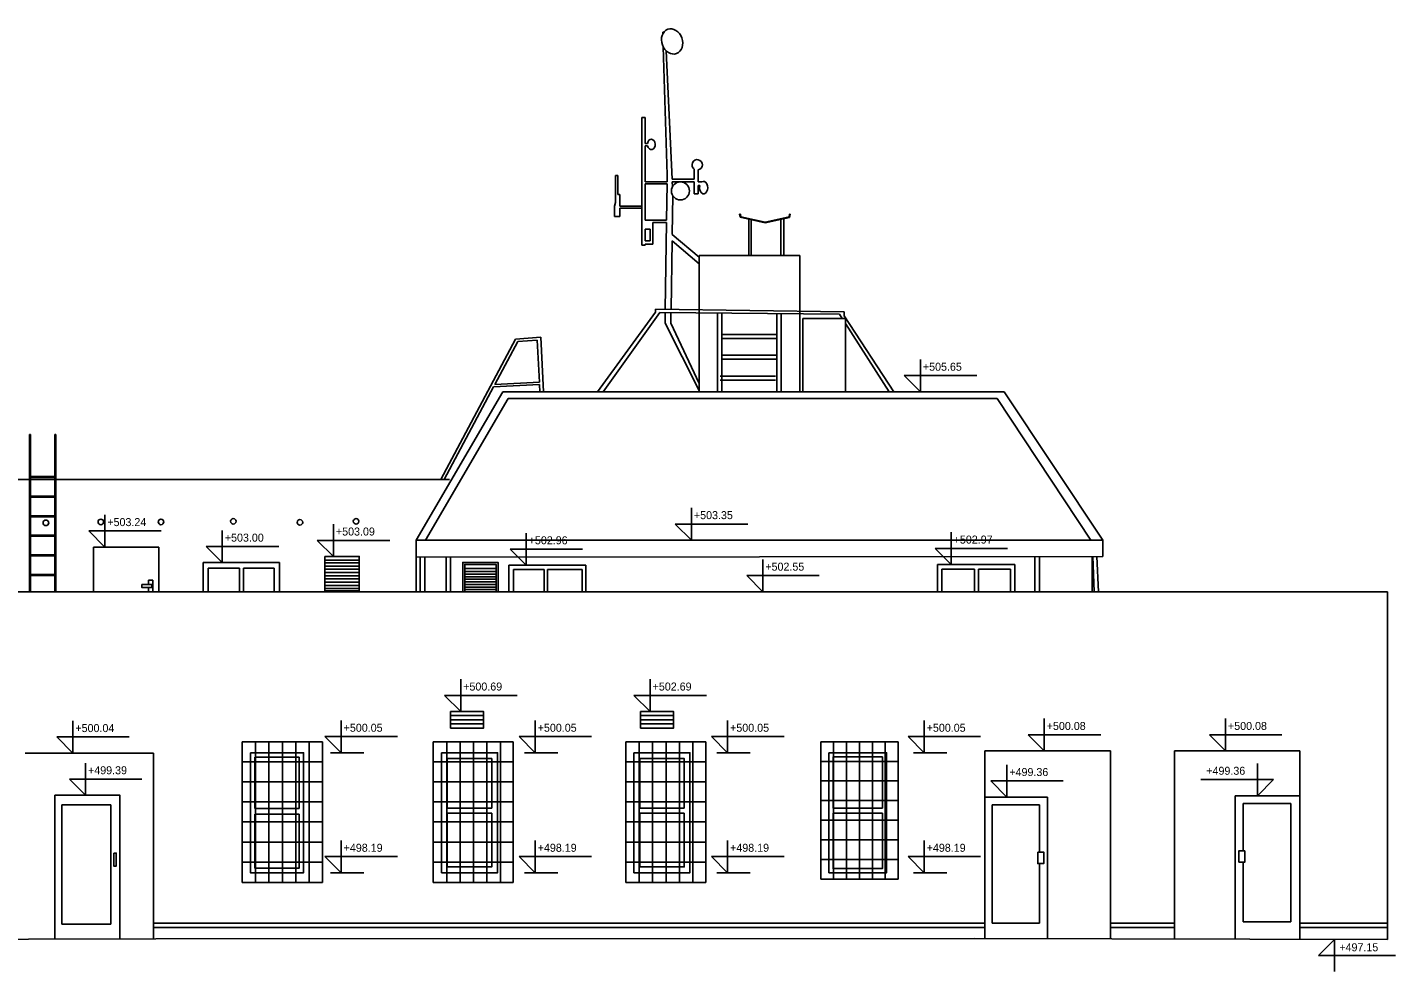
# Model space of a CAD drawing. Extents: x 224 to 311.2, y 493.1 to 511.4.
# Drawn here: x 290.02 to 311.23, y 496.65 to 511.3 of the extents above; entities that cross this region are included whole.
import ezdxf

# ---------------------------------------------------------------- set-up
doc = ezdxf.new("R2010")
doc.units = 0
for name, color, linetype in [('antena', 7, 'Continuous'), ('dvere', 7, 'Continuous'), ('mriz', 7, 'Continuous'), ('okap', 7, 'Continuous'), ('okna', 7, 'Continuous'), ('strecha_sikma', 7, 'Continuous'), ('teren', 7, 'Continuous'), ('vyustky_vzduchotechniky', 7, 'Continuous'), ('zakl_tenka', 7, 'Continuous'), ('zebrik', 7, 'Continuous'), ('znaceni', 7, 'Continuous')]:
    doc.layers.add(name, color=color, linetype=linetype)

msp = doc.modelspace()

# ---------------------------------------------------------------- linework, layer by layer
at = {"layer": 'antena'}
for p, q in [((299.871, 511.222), (299.887, 511.222)), ((299.872, 511.198), (299.871, 511.222)), ((299.939, 509.008), (299.878, 510.995)), ((299.924, 510.933), (300.015, 508.944)), ((299.547, 509.897), (299.547, 507.917)), ((299.547, 509.897), (299.597, 509.897)), ((299.597, 509.897), (299.597, 509.497)), ((299.597, 509.497), (299.634, 509.497)), ((299.597, 509.457), (299.636, 509.457)), ((299.597, 509.457), (299.597, 508.899)), ((299.138, 508.999), (299.138, 508.579)), ((299.172, 508.999), (299.138, 508.999)), ((299.172, 508.704), (299.172, 508.999)), ((299.938, 508.899), (299.939, 509.008)), ((300.358, 509.1), (300.358, 508.944)), ((300.418, 509.087), (300.418, 508.899)), ((299.597, 508.899), (299.938, 508.899)), ((299.597, 508.868), (299.938, 508.868)), ((299.597, 508.868), (299.597, 508.308)), ((299.93, 508.308), (299.938, 508.868)), ((300.015, 508.944), (300.358, 508.944)), ((300.017, 508.899), (300.358, 508.899)), ((300.017, 508.899), (300.021, 508.828)), ((300.358, 508.899), (300.358, 508.716)), ((300.478, 508.899), (300.418, 508.899)), ((300.445, 508.842), (300.418, 508.842)), ((300.418, 508.842), (300.418, 508.716)), ((299.138, 508.579), (299.123, 508.524)), ((299.203, 508.704), (299.172, 508.704)), ((299.203, 508.524), (299.203, 508.704)), ((300.024, 508.689), (300.015, 508.085)), ((300.358, 508.716), (300.418, 508.716)), ((299.123, 508.524), (299.123, 508.364)), ((299.123, 508.364), (299.203, 508.364)), ((299.547, 508.524), (299.203, 508.524)), ((299.547, 508.493), (299.203, 508.493)), ((299.203, 508.364), (299.203, 508.493)), ((299.93, 508.308), (299.597, 508.308)), ((299.597, 508.168), (299.677, 508.168)), ((299.597, 508.168), (299.597, 507.988)), ((299.677, 508.168), (299.677, 507.988)), ((299.718, 508.273), (299.929, 508.273)), ((299.718, 508.273), (299.718, 507.933)), ((299.91, 506.923), (299.929, 508.273)), ((299.677, 507.988), (299.597, 507.988)), ((300.014, 507.986), (299.999, 506.922)), ((300.014, 507.986), (300.437, 507.63)), ((300.015, 508.085), (300.437, 507.731)), ((299.547, 507.917), (299.597, 507.917)), ((299.718, 507.933), (299.597, 507.933)), ((299.597, 507.933), (299.597, 507.917)), ((299.907, 506.709), (299.909, 506.872)), ((299.907, 506.709), (300.437, 505.668)), ((299.998, 506.871), (299.996, 506.709)), ((300.437, 505.772), (299.996, 506.709))]:
    msp.add_line(p, q, dxfattribs=at)
msp.add_circle((300.144, 508.761), 0.14, dxfattribs=at)
msp.add_arc((300.404, 509.166), 0.08, 280.3791, 235.261, dxfattribs=at)
msp.add_ellipse((300.016, 511.078), major_axis=(-0.068, 0.188), ratio=0.8, dxfattribs=at)
for centre, major_axis, ratio, start_param, end_param in [((299.693, 509.482), (0, 0.08), 0.75, 1.88862, 7.665365), ((300.504, 508.812), (0, 0.096), 0.653945, 1.246279, 6.710051)]:
    msp.add_ellipse(centre, major_axis=major_axis, ratio=ratio, start_param=start_param, end_param=end_param, dxfattribs=at)
at = {"layer": 'dvere'}
for p, q in [((290.557, 499.241), (291.314, 499.241)), ((290.557, 499.241), (290.557, 497.391)), ((291.314, 499.241), (291.314, 497.391)), ((290.557, 497.391), (291.314, 497.391))]:
    msp.add_line(p, q, dxfattribs=at)
msp.add_lwpolyline([(291.362, 498.493), (291.4, 498.493), (291.4, 498.29), (291.362, 498.29)], close=True, dxfattribs=at)
at = {"layer": 'mriz'}
for p, q in [((293.353, 500.219), (294.597, 500.219)), ((293.353, 500.219), (293.353, 498.039)), ((293.56, 500.219), (293.56, 498.039)), ((293.767, 500.219), (293.767, 498.039)), ((293.974, 500.219), (293.974, 498.039)), ((294.181, 500.219), (294.181, 498.039)), ((294.388, 500.219), (294.388, 498.039)), ((294.597, 500.219), (294.597, 498.039)), ((296.314, 500.219), (297.554, 500.219)), ((296.314, 500.219), (296.314, 498.039)), ((296.522, 500.219), (296.522, 498.039)), ((296.73, 500.219), (296.73, 498.039)), ((296.938, 500.219), (296.938, 498.039)), ((297.146, 500.219), (297.146, 498.039)), ((297.354, 500.219), (297.354, 498.039)), ((297.554, 500.219), (297.554, 498.039)), ((299.297, 500.219), (300.537, 500.219)), ((299.297, 500.219), (299.297, 498.039)), ((299.505, 500.219), (299.505, 498.039)), ((299.713, 500.219), (299.713, 498.039)), ((299.921, 500.219), (299.921, 498.039)), ((300.129, 500.219), (300.129, 498.039)), ((300.337, 500.219), (300.337, 498.039)), ((300.537, 500.219), (300.537, 498.039)), ((302.319, 500.219), (303.519, 500.219)), ((302.319, 500.219), (302.319, 498.089)), ((302.519, 500.219), (302.519, 498.089)), ((302.719, 500.219), (302.719, 498.089)), ((302.919, 500.219), (302.919, 498.089)), ((303.119, 500.219), (303.119, 498.089)), ((303.319, 500.219), (303.319, 498.089)), ((303.519, 500.219), (303.519, 498.089)), ((293.353, 499.908), (294.597, 499.908)), ((296.314, 499.908), (297.554, 499.908)), ((299.297, 499.908), (300.537, 499.908)), ((302.319, 499.915), (303.519, 499.915)), ((293.353, 499.597), (294.597, 499.597)), ((296.314, 499.597), (297.554, 499.597)), ((299.297, 499.597), (300.537, 499.597)), ((302.319, 499.611), (303.519, 499.611)), ((293.353, 499.286), (294.597, 499.286)), ((296.314, 499.286), (297.554, 499.286)), ((299.297, 499.286), (300.537, 499.286)), ((302.319, 499.307), (303.519, 499.307)), ((293.353, 498.975), (294.597, 498.975)), ((296.314, 498.975), (297.554, 498.975)), ((299.297, 498.975), (300.537, 498.975)), ((302.319, 499.003), (303.519, 499.003)), ((293.353, 498.664), (294.597, 498.664)), ((296.314, 498.664), (297.554, 498.664)), ((299.297, 498.664), (300.537, 498.664)), ((302.319, 498.699), (303.519, 498.699)), ((302.319, 498.395), (303.519, 498.395)), ((293.353, 498.353), (294.597, 498.353)), ((296.314, 498.353), (297.554, 498.353)), ((299.297, 498.353), (300.537, 498.353)), ((293.353, 498.039), (294.597, 498.039)), ((296.314, 498.039), (297.554, 498.039)), ((299.297, 498.039), (300.537, 498.039)), ((302.319, 498.089), (303.519, 498.089))]:
    msp.add_line(p, q, dxfattribs=at)
at = {"layer": 'okap'}
for p, q in [((296.048, 503.345), (296.048, 503.081)), ((306.689, 503.345), (306.689, 503.091)), ((306.689, 503.091), (296.048, 503.081)), ((296.048, 503.081), (296.048, 502.546)), ((296.112, 503.081), (296.112, 502.546)), ((296.512, 503.082), (296.512, 502.546)), ((296.578, 503.082), (296.578, 502.546)), ((305.638, 503.09), (305.638, 502.546)), ((305.712, 503.09), (305.712, 502.546)), ((306.534, 503.091), (306.557, 502.546)), ((306.601, 503.091), (306.625, 502.546))]:
    msp.add_line(p, q, dxfattribs=at)
at = {"layer": 'okna'}
for p, q in [((292.824, 502.912), (292.824, 502.546)), ((292.824, 502.912), (293.308, 502.912)), ((293.308, 502.912), (293.308, 502.546)), ((293.372, 502.912), (293.372, 502.546)), ((293.372, 502.912), (293.849, 502.912)), ((293.849, 502.912), (293.849, 502.546)), ((297.558, 502.889), (298.033, 502.889)), ((297.558, 502.889), (297.558, 502.546)), ((298.033, 502.889), (298.033, 502.546)), ((298.086, 502.889), (298.086, 502.546)), ((298.086, 502.889), (298.621, 502.889)), ((298.621, 502.889), (298.621, 502.546)), ((304.196, 502.897), (304.196, 502.546)), ((304.196, 502.897), (304.7, 502.897)), ((304.7, 502.897), (304.7, 502.546)), ((304.764, 502.897), (304.764, 502.546)), ((304.764, 502.897), (305.26, 502.897)), ((305.26, 502.897), (305.26, 502.546)), ((309.603, 499.26), (308.869, 499.26)), ((308.869, 499.26), (308.869, 498.529)), ((309.603, 499.26), (309.603, 497.426)), ((293.55, 499.183), (294.233, 499.183)), ((293.55, 499.097), (294.233, 499.097)), ((296.531, 499.191), (297.221, 499.191)), ((296.531, 499.111), (297.221, 499.111)), ((299.513, 499.191), (300.203, 499.191)), ((299.513, 499.111), (300.203, 499.111)), ((302.511, 499.191), (303.275, 499.191)), ((302.511, 499.111), (303.275, 499.111)), ((304.975, 499.239), (305.709, 499.239)), ((304.975, 499.239), (304.975, 497.405)), ((305.709, 499.239), (305.709, 498.508)), ((305.709, 498.331), (305.709, 497.405)), ((308.869, 498.352), (308.869, 497.426)), ((304.975, 497.405), (305.709, 497.405)), ((309.603, 497.426), (308.869, 497.426))]:
    msp.add_line(p, q, dxfattribs=at)
for points in [[(293.55, 499.183), (293.55, 499.979), (294.233, 499.979), (294.233, 499.183)], [(296.531, 499.191), (296.531, 499.959), (297.221, 499.959), (297.221, 499.191)], [(299.513, 499.191), (299.513, 499.959), (300.203, 499.959), (300.203, 499.191)], [(302.511, 499.191), (302.511, 499.984), (303.275, 499.984), (303.275, 499.191)], [(294.233, 499.097), (294.233, 498.257), (293.55, 498.257), (293.55, 499.097)], [(297.221, 499.111), (297.221, 498.277), (296.531, 498.277), (296.531, 499.111)], [(300.203, 499.111), (300.203, 498.277), (299.513, 498.277), (299.513, 499.111)], [(303.275, 499.111), (303.275, 498.252), (302.511, 498.252), (302.511, 499.111)]]:
    msp.add_lwpolyline(points, dxfattribs=at)
for points in [[(305.684, 498.508), (305.777, 498.508), (305.777, 498.331), (305.684, 498.331)], [(308.894, 498.529), (308.801, 498.529), (308.801, 498.352), (308.894, 498.352)]]:
    msp.add_lwpolyline(points, close=True, dxfattribs=at)
at = {"layer": 'strecha_sikma'}
for p, q in [((297.391, 505.647), (296.048, 503.345)), ((297.391, 505.647), (305.163, 505.647)), ((305.163, 505.647), (306.689, 503.345)), ((297.475, 505.54), (296.194, 503.345)), ((297.475, 505.54), (305.054, 505.54)), ((305.054, 505.54), (306.508, 503.345)), ((296.048, 503.345), (306.689, 503.345))]:
    msp.add_line(p, q, dxfattribs=at)
at = {"layer": 'teren'}
msp.add_line((304.698, 497.168), (311.105, 497.152), dxfattribs=at)
msp.add_lwpolyline([(260.099, 497.175), (263.904, 497.145), (275.27, 497.123), (276.223, 497.121), (292.012, 497.161), (304.698, 497.168)], dxfattribs=at)
at = {"layer": 'vyustky_vzduchotechniky'}
for p, q in [((294.63, 503.033), (295.166, 503.033)), ((294.63, 502.993), (295.166, 502.993)), ((294.63, 502.943), (295.166, 502.943)), ((294.63, 502.893), (295.166, 502.893)), ((296.8, 502.908), (297.286, 502.908)), ((296.8, 502.858), (297.286, 502.858)), ((294.63, 502.843), (295.166, 502.843)), ((294.63, 502.793), (295.166, 502.793)), ((294.63, 502.743), (295.166, 502.743)), ((294.63, 502.693), (295.166, 502.693)), ((294.63, 502.643), (295.166, 502.643)), ((296.8, 502.818), (297.286, 502.818)), ((296.8, 502.778), (297.286, 502.778)), ((296.8, 502.738), (297.286, 502.738)), ((296.8, 502.698), (297.286, 502.698)), ((296.8, 502.658), (297.286, 502.658)), ((294.63, 502.593), (295.166, 502.593)), ((296.8, 502.618), (297.286, 502.618)), ((296.8, 502.578), (297.286, 502.578)), ((296.581, 500.624), (297.092, 500.624)), ((296.581, 500.56), (297.092, 500.56)), ((299.526, 500.624), (300.037, 500.624)), ((299.526, 500.56), (300.037, 500.56)), ((296.581, 500.496), (297.092, 500.496)), ((299.526, 500.496), (300.037, 500.496))]:
    msp.add_line(p, q, dxfattribs=at)
for points in [[(294.63, 503.092), (295.166, 503.092), (295.166, 502.557), (294.63, 502.557)], [(296.581, 500.688), (297.092, 500.688), (297.092, 500.431), (296.581, 500.431)], [(299.526, 500.688), (300.037, 500.688), (300.037, 500.431), (299.526, 500.431)]]:
    msp.add_lwpolyline(points, close=True, dxfattribs=at)
for points in [[(296.769, 502.546), (296.769, 503), (297.317, 503), (297.317, 502.546)], [(296.8, 502.546), (296.8, 502.969), (297.286, 502.969), (297.286, 502.546)]]:
    msp.add_lwpolyline(points, dxfattribs=at)
at = {"layer": 'zakl_tenka'}
for p, q in [((300.437, 507.76), (300.437, 505.647)), ((301.994, 507.76), (301.994, 505.647)), ((302.043, 506.782), (302.043, 505.647)), ((302.704, 506.782), (302.043, 506.782)), ((302.704, 506.782), (302.704, 505.647)), ((281.454, 504.283), (296.565, 504.283)), ((291.046, 503.237), (291.046, 502.546)), ((291.046, 503.237), (292.057, 503.237)), ((292.057, 503.237), (292.057, 502.546)), ((296.184, 503.081), (296.184, 502.546)), ((306.524, 503.091), (306.524, 502.546)), ((292.745, 502.996), (293.931, 502.996)), ((292.745, 502.996), (292.745, 502.546)), ((293.931, 502.996), (293.931, 502.546)), ((297.483, 502.955), (297.483, 502.546)), ((297.483, 502.955), (298.679, 502.955)), ((298.679, 502.955), (298.679, 502.546)), ((304.131, 502.967), (304.131, 502.546)), ((304.131, 502.967), (305.33, 502.967)), ((305.33, 502.967), (305.33, 502.546)), ((279.583, 502.546), (311.105, 502.546)), ((311.105, 502.546), (311.105, 497.152)), ((289.987, 500.043), (291.975, 500.043)), ((291.975, 500.043), (291.975, 497.161)), ((304.864, 500.077), (306.81, 500.077)), ((304.864, 500.077), (304.864, 497.167)), ((306.81, 500.077), (306.81, 497.163)), ((307.8, 500.077), (309.746, 500.077)), ((307.8, 500.077), (307.8, 497.16)), ((309.746, 500.077), (309.746, 497.155)), ((304.864, 499.361), (305.833, 499.361)), ((305.833, 499.361), (305.833, 497.165)), ((309.746, 499.382), (308.745, 499.382)), ((308.745, 499.382), (308.745, 497.158)), ((291.975, 497.405), (304.864, 497.405)), ((291.975, 497.339), (304.864, 497.339)), ((306.81, 497.405), (307.8, 497.405)), ((306.81, 497.339), (307.8, 497.339)), ((309.746, 497.405), (311.105, 497.405)), ((309.746, 497.339), (311.105, 497.339))]:
    msp.add_line(p, q, dxfattribs=at)
for points in [[(301.994, 507.76), (300.437, 507.76)], [(291.9, 502.659), (291.9, 502.722), (291.964, 502.722), (291.964, 502.546)], [(291.9, 502.546), (291.9, 502.612)], [(290.449, 497.157), (290.449, 499.389), (291.456, 499.389), (291.456, 497.16)]]:
    msp.add_lwpolyline(points, dxfattribs=at)
for points in [[(291.796, 502.659), (291.951, 502.659), (291.951, 502.612), (291.796, 502.612)], [(293.48, 500.048), (294.302, 500.048), (294.302, 498.188), (293.48, 498.188)], [(296.442, 500.048), (297.31, 500.048), (297.31, 498.188), (296.442, 498.188)], [(299.424, 500.048), (300.292, 500.048), (300.292, 498.188), (299.424, 498.188)], [(302.447, 500.048), (303.339, 500.048), (303.339, 498.188), (302.447, 498.188)]]:
    msp.add_lwpolyline(points, close=True, dxfattribs=at)
for centre in [(290.309, 503.613), (291.161, 503.628), (292.093, 503.628), (293.214, 503.637), (294.247, 503.621), (295.117, 503.637)]:
    msp.add_circle(centre, 0.0431, dxfattribs=at)
at = {"layer": 'zebrik'}
for p, q in [((301.059, 508.399), (301.068, 508.351)), ((301.059, 508.399), (301.074, 508.399)), ((301.074, 508.4), (301.081, 508.358)), ((301.828, 508.356), (301.836, 508.398)), ((301.836, 508.348), (301.847, 508.398)), ((301.847, 508.398), (301.836, 508.398)), ((301.068, 508.351), (301.459, 508.268)), ((301.081, 508.358), (301.46, 508.278)), ((301.202, 508.322), (301.202, 507.76)), ((301.242, 508.314), (301.242, 507.76)), ((301.459, 508.268), (301.836, 508.348)), ((301.46, 508.278), (301.828, 508.356)), ((301.702, 508.32), (301.702, 507.76)), ((301.747, 508.329), (301.747, 507.76)), ((299.756, 506.881), (298.86, 505.647)), ((299.756, 506.926), (302.683, 506.883)), ((299.756, 506.926), (299.756, 506.881)), ((302.683, 506.883), (302.683, 506.824)), ((299.823, 506.873), (298.945, 505.647)), ((299.823, 506.873), (302.609, 506.85)), ((300.721, 506.865), (300.721, 505.647)), ((300.786, 506.865), (300.786, 505.647)), ((301.641, 506.858), (301.641, 505.647)), ((301.706, 506.857), (301.706, 505.647)), ((302.609, 506.85), (302.653, 506.782)), ((302.683, 506.824), (303.452, 505.647)), ((302.704, 506.702), (303.381, 505.647)), ((297.588, 506.463), (296.428, 504.283)), ((297.588, 506.463), (297.978, 506.491)), ((297.978, 506.491), (298.022, 505.647)), ((300.786, 506.534), (301.641, 506.534)), ((300.786, 506.474), (301.641, 506.474)), ((297.623, 506.427), (297.268, 505.759)), ((297.623, 506.427), (297.925, 506.448)), ((297.925, 506.448), (297.959, 505.795)), ((300.783, 506.214), (301.638, 506.214)), ((300.783, 506.154), (301.638, 506.154)), ((300.761, 505.888), (301.616, 505.888)), ((300.761, 505.828), (301.616, 505.828)), ((297.247, 505.72), (296.483, 504.283)), ((297.247, 505.72), (297.961, 505.757)), ((297.268, 505.759), (297.959, 505.795)), ((297.961, 505.757), (297.967, 505.647)), ((290.056, 504.984), (290.056, 502.546)), ((290.056, 504.984), (290.071, 504.984)), ((290.071, 504.984), (290.071, 504.334)), ((290.446, 504.984), (290.461, 504.984)), ((290.446, 504.984), (290.446, 504.334)), ((290.461, 504.984), (290.461, 502.546)), ((290.071, 504.334), (290.446, 504.334)), ((290.071, 504.319), (290.446, 504.319)), ((290.071, 504.319), (290.071, 504.029)), ((290.446, 504.319), (290.446, 504.029)), ((290.071, 504.029), (290.446, 504.029)), ((290.071, 504.014), (290.446, 504.014)), ((290.071, 504.014), (290.071, 503.724)), ((290.446, 504.014), (290.446, 503.724)), ((290.071, 503.724), (290.446, 503.724)), ((290.071, 503.709), (290.446, 503.709)), ((290.071, 503.709), (290.071, 503.42)), ((290.446, 503.709), (290.446, 503.42)), ((290.071, 503.42), (290.446, 503.42)), ((290.071, 503.405), (290.446, 503.405)), ((290.071, 503.405), (290.071, 503.115)), ((290.446, 503.405), (290.446, 503.115)), ((290.071, 503.115), (290.446, 503.115)), ((290.071, 503.1), (290.446, 503.1)), ((290.071, 503.1), (290.071, 502.81)), ((290.446, 503.1), (290.446, 502.81)), ((290.071, 502.81), (290.446, 502.81)), ((290.071, 502.795), (290.446, 502.795)), ((290.071, 502.795), (290.071, 502.546)), ((290.446, 502.795), (290.446, 502.546))]:
    msp.add_line(p, q, dxfattribs=at)
at = {"layer": 'znaceni'}
for p, q in [((303.863, 506.147), (303.863, 505.647)), ((303.863, 505.897), (303.613, 505.897)), ((303.613, 505.897), (303.863, 505.647)), ((303.863, 505.647), (303.863, 505.897)), ((303.863, 505.897), (304.738, 505.897)), ((291.222, 503.737), (291.222, 503.237)), ((300.314, 503.845), (300.314, 503.345)), ((291.222, 503.487), (290.972, 503.487)), ((290.972, 503.487), (291.222, 503.237)), ((291.222, 503.237), (291.222, 503.487)), ((291.222, 503.487), (292.097, 503.487)), ((293.043, 503.496), (293.043, 502.996)), ((294.765, 503.592), (294.765, 503.092)), ((300.314, 503.595), (300.064, 503.595)), ((300.064, 503.595), (300.314, 503.345)), ((300.314, 503.345), (300.314, 503.595)), ((300.314, 503.595), (301.189, 503.595)), ((294.765, 503.342), (294.515, 503.342)), ((294.515, 503.342), (294.765, 503.092)), ((294.765, 503.092), (294.765, 503.342)), ((294.765, 503.342), (295.64, 503.342)), ((297.753, 503.455), (297.753, 502.955)), ((304.341, 503.467), (304.341, 502.967)), ((293.043, 503.246), (292.793, 503.246)), ((292.793, 503.246), (293.043, 502.996)), ((293.043, 502.996), (293.043, 503.246)), ((293.043, 503.246), (293.918, 503.246)), ((297.753, 503.205), (297.503, 503.205)), ((297.503, 503.205), (297.753, 502.955)), ((297.753, 502.955), (297.753, 503.205)), ((297.753, 503.205), (298.628, 503.205)), ((304.341, 503.217), (304.091, 503.217)), ((304.091, 503.217), (304.341, 502.967)), ((304.341, 502.967), (304.341, 503.217)), ((304.341, 503.217), (305.216, 503.217)), ((301.421, 503.046), (301.421, 502.546)), ((301.421, 502.796), (301.171, 502.796)), ((301.171, 502.796), (301.421, 502.546)), ((301.421, 502.546), (301.421, 502.796)), ((301.421, 502.796), (302.296, 502.796)), ((296.738, 501.188), (296.738, 500.688)), ((299.674, 501.188), (299.674, 500.688)), ((296.738, 500.938), (296.488, 500.938)), ((296.488, 500.938), (296.738, 500.688)), ((296.738, 500.688), (296.738, 500.938)), ((296.738, 500.938), (297.613, 500.938)), ((299.674, 500.938), (299.424, 500.938)), ((299.424, 500.938), (299.674, 500.688)), ((299.674, 500.688), (299.674, 500.938)), ((299.674, 500.938), (300.549, 500.938)), ((290.727, 500.543), (290.727, 500.043)), ((294.885, 500.548), (294.885, 500.048)), ((297.893, 500.548), (297.893, 500.048)), ((300.876, 500.548), (300.876, 500.048)), ((303.923, 500.548), (303.923, 500.048)), ((305.783, 500.577), (305.783, 500.077)), ((308.593, 500.577), (308.593, 500.077)), ((305.783, 500.327), (305.533, 500.327)), ((305.533, 500.327), (305.783, 500.077)), ((305.783, 500.077), (305.783, 500.327)), ((305.783, 500.327), (306.658, 500.327)), ((308.593, 500.327), (308.343, 500.327)), ((308.343, 500.327), (308.593, 500.077)), ((308.593, 500.077), (308.593, 500.327)), ((308.593, 500.327), (309.468, 500.327)), ((290.727, 500.293), (290.477, 500.293)), ((290.477, 500.293), (290.727, 500.043)), ((290.727, 500.043), (290.727, 500.293)), ((290.727, 500.293), (291.602, 500.293)), ((294.885, 500.298), (294.635, 500.298)), ((294.635, 500.298), (294.885, 500.048)), ((294.885, 500.048), (294.885, 500.298)), ((294.885, 500.298), (295.76, 500.298)), ((297.893, 500.298), (297.643, 500.298)), ((297.643, 500.298), (297.893, 500.048)), ((297.893, 500.048), (297.893, 500.298)), ((297.893, 500.298), (298.768, 500.298)), ((300.876, 500.298), (300.626, 500.298)), ((300.626, 500.298), (300.876, 500.048)), ((300.876, 500.048), (300.876, 500.298)), ((300.876, 500.298), (301.75, 500.298)), ((303.923, 500.298), (303.673, 500.298)), ((303.673, 500.298), (303.923, 500.048)), ((303.923, 500.048), (303.923, 500.298)), ((303.923, 500.298), (304.797, 500.298)), ((290.923, 499.889), (290.923, 499.389)), ((294.719, 500.048), (295.235, 500.048)), ((297.727, 500.048), (298.242, 500.048)), ((300.709, 500.048), (301.225, 500.048)), ((303.756, 500.048), (304.272, 500.048)), ((309.088, 499.882), (309.088, 499.382)), ((305.203, 499.861), (305.203, 499.361)), ((290.923, 499.639), (290.673, 499.639)), ((290.673, 499.639), (290.923, 499.389)), ((290.923, 499.389), (290.923, 499.639)), ((290.923, 499.639), (291.798, 499.639)), ((305.203, 499.611), (304.953, 499.611)), ((304.953, 499.611), (305.203, 499.361)), ((305.203, 499.361), (305.203, 499.611)), ((305.203, 499.611), (306.078, 499.611)), ((309.088, 499.632), (308.213, 499.632)), ((309.088, 499.632), (309.338, 499.632)), ((309.338, 499.632), (309.088, 499.382)), ((309.088, 499.382), (309.088, 499.632)), ((294.885, 498.688), (294.885, 498.188)), ((297.893, 498.688), (297.893, 498.188)), ((300.876, 498.688), (300.876, 498.188)), ((303.923, 498.688), (303.923, 498.188)), ((294.885, 498.438), (294.635, 498.438)), ((294.635, 498.438), (294.885, 498.188)), ((294.885, 498.188), (294.885, 498.438)), ((294.885, 498.438), (295.76, 498.438)), ((297.893, 498.438), (297.643, 498.438)), ((297.643, 498.438), (297.893, 498.188)), ((297.893, 498.188), (297.893, 498.438)), ((297.893, 498.438), (298.768, 498.438)), ((300.876, 498.438), (300.626, 498.438)), ((300.626, 498.438), (300.876, 498.188)), ((300.876, 498.188), (300.876, 498.438)), ((300.876, 498.438), (301.75, 498.438)), ((303.923, 498.438), (303.673, 498.438)), ((303.673, 498.438), (303.923, 498.188)), ((303.923, 498.188), (303.923, 498.438)), ((303.923, 498.438), (304.797, 498.438)), ((294.719, 498.188), (295.235, 498.188)), ((297.727, 498.188), (298.242, 498.188)), ((300.709, 498.188), (301.225, 498.188)), ((303.756, 498.188), (304.272, 498.188)), ((310.034, 496.904), (310.284, 497.154)), ((310.284, 496.654), (310.284, 497.154)), ((310.284, 496.904), (310.034, 496.904)), ((310.284, 496.904), (311.23, 496.904))]:
    msp.add_line(p, q, dxfattribs=at)

# ---------------------------------------------------------------- texts
for s, p in [('+505.65', (303.902, 505.972)), ('+503.35', (300.353, 503.671)), ('+503.24', (291.261, 503.563)), ('+503.09', (294.804, 503.417)), ('+503.00', (293.082, 503.322)), ('+502.96', (297.792, 503.281)), ('+502.97', (304.379, 503.292)), ('+502.55', (301.46, 502.872)), ('+500.69', (296.777, 501.013)), ('+502.69', (299.713, 501.013)), ('+500.08', (305.822, 500.402)), ('+500.08', (308.631, 500.402)), ('+500.04', (290.766, 500.369)), ('+500.05', (294.924, 500.374)), ('+500.05', (297.932, 500.374)), ('+500.05', (300.914, 500.374)), ('+500.05', (303.961, 500.374)), ('+499.39', (290.962, 499.715)), ('+499.36', (305.242, 499.687)), ('+499.36', (308.295, 499.707)), ('+498.19', (294.924, 498.513)), ('+498.19', (297.932, 498.513)), ('+498.19', (300.914, 498.513)), ('+498.19', (303.961, 498.513)), ('+497.15', (310.357, 496.97))]:
    msp.add_text(s, height=0.124, dxfattribs=at).set_placement(p)

doc.saveas('drawing.dxf')
